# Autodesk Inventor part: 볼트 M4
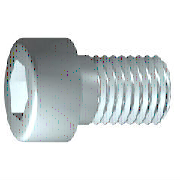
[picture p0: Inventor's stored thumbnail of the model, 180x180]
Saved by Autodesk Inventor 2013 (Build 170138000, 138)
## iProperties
Created: 2012-02
Part Number: 볼트 M4
Material: 스테인리스강
Description: 6각 소켓 머리 캡 나사
Document SubType Name: Modeling
Standard: ISO 4762
Designer: mduedu
Standard Revision: Fourth edition 2004-03-01
Standards Organization: ISO
Language: ko-KR
Size Designation: M4 x 16
Categories: <MemberInstance><Categories><Category DisplayName="조임쇠" InternalName="e4da775c-781d-43d5-af7c-5136215cf5a6" Mnemonic="FSTN"><Category DisplayName="볼트" InternalN
Density: 7.75 g/cm^3
IsCustomPart: 0
Author: mduedu
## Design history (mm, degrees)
sketch "스케치1"
  geometry: L1 (-1, 0)-(16, 0); L2 (16, 0)-(16, 2); L3 (16, 2)-(1.75, 2); L4 (1.75, 2)-(1.32, 2); L5 (1.32, 2)-(0, 2); L6 (0, 2)-(0, 3.5); L7 (0, 3.5)-(-4, 3.5); L8 (-4, 3.5)-(-4, 1.732); L9 (-4, 1.732)-(-2, 1.732); L10 (-2, 1.732)-(-1, 0); L11 (-8, 0)-(20, 0) reference; L12 (0, -0.7)-(0, 4.2) reference; L13 (1.75, 2)-(0, 2)
  constraints: 22 end point, 6 parallel, 2 collinear, 2 perpendicular, 1 horizontal, 1 point on line
  dimensions: "d1" = 14.25 distance from line of L3.end L2 (= GEL); "d2" = 0.42952 distance of L4.end L3.end (computed from GAL); "d3" = 4 distance between parallel lines of L8 L6 (= KOH); "d4" = 2 distance of L8.end L9.end (= INTI); "d5" = 60 deg angle of L10 L1; "d6" = 4 diameter of L3 L1 (= GD); "d7" = 4 diameter of L5 L1 (= BDM); "d8" = 3.4641 diameter of L9 L1 (= 1.1547 x SW); "d9" = 7 diameter of L7 L1 (= KOD); "d26" = 16 distance between parallel lines of L12 L2 (= NLG)
revolve "본체" sketch "스케치1" stored, may be unused: angle "d10" = 90 deg
sketch "스케치2"
  geometry: L1 (0, -4.9)-(0, 4.9) reference; L2 (-4.9, 0)-(4.9, 0) reference; L3 (1.732, 0)-(0.866, -1.5); L4 (0.866, -1.5)-(-0.866, -1.5); L5 (-0.866, -1.5)-(-1.732, 0); L6 (-1.732, 0)-(-0.866, 1.5); L7 (-0.866, 1.5)-(0.866, 1.5); L8 (0.866, 1.5)-(1.732, 0); 2 further points
  constraints: 12 end point, 1 coincident, 1 horizontal alignment, 1 point on line, 12 other
extrude "슬롯" join sketch "스케치2" stored distance "d11" = 10; taper "d12" = 0 deg
workplane "Work Plane1"
fillet "Fillet2" dims "d30" = 0.1 (= R)
body "Solid1"
fillet "모깎기1" dims "d17" = 0.4 (= RR)
feature "스레드" dims "d13" = 14.25 (= GEL), "d14" = 0
chamfer "모따기1" distance "d15" = 0.42941 (= -0.5 x SPD + 0.5 x GD); stored, may be unused: second distance "d16" = 0.42941 (= GUL), angle "d27" = 45 deg
other parameters: "GD" = 4 [user parameter; used in 2 equation terms], "NLG" = 16 [user parameter; used in 1 equation term], "GEL" = 14.25 [user parameter; used in 2 equation terms], "KOD" = 7 [user parameter; used in 1 equation term], "KOH" = 4 [user parameter; used in 1 equation term], "INTI" = 2 [user parameter; used in 1 equation term], "GAL" = 0.42941 (= 0.61345 x PTC) [user parameter; used in 1 equation term], "GUL" = 0.42941 (= 0.61345 x PTC) [user parameter; used in 1 equation term], "BDM" = 4 (= NND) [user parameter; used in 1 equation term], "SW" = 3 [user parameter; used in 2 equation terms], "RR" = 0.4 [user parameter; used in 1 equation term], "SPD" = 3.14117 (= NND - 1.2269 x PTC) [user parameter; used in 1 equation term], "d19" = 0, "d28" = 0, "d29" = 0, "R" = 0.1 [user parameter; used in 1 equation term], "TOA" = 30 deg [user parameter], "GD1" = 3.14117 (= THREADDIA - 1.2269 x PTC) [user parameter], "THREADDIA" = 4 [user parameter; used in 1 equation term], "FAWI" = 45 deg [user parameter], "TPU" = 14.28571 (computed from PTC) [user parameter], "PTC" = 0.7 [user parameter; used in 5 equation terms], "NND" = 4 [user parameter; used in 2 equation terms], "E0" = 3.465 (= 1.155 x SW) [user parameter]
